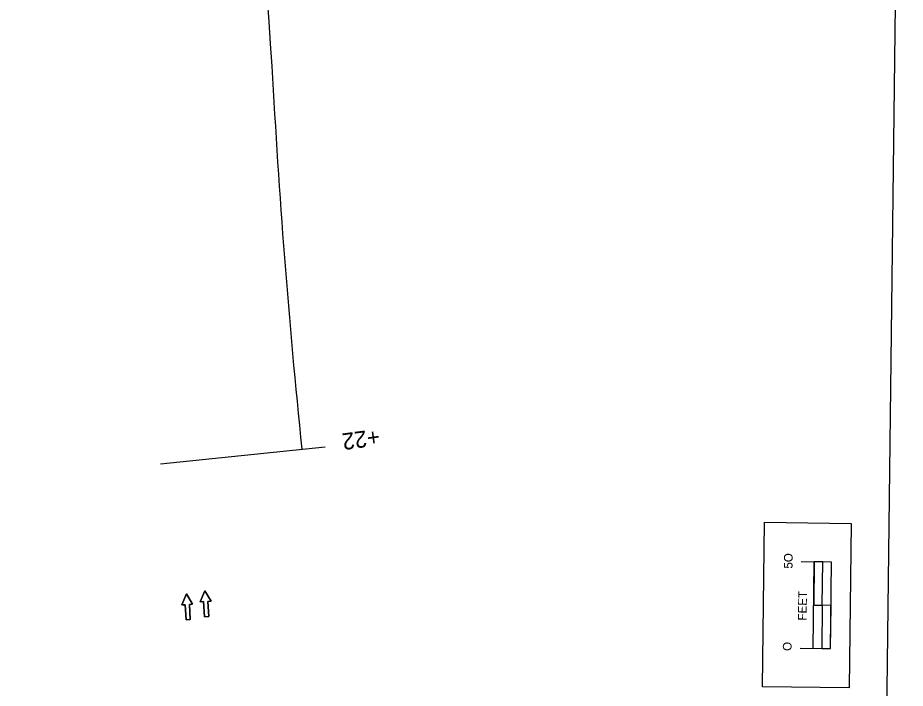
# Model space of a CAD drawing. Extents: x 4959127 to 4960275, y 3872379 to 3884458.
# Drawn here: x 4959633 to 4960146, y 3873092 to 3873480 of the extents above; entities that cross this region are included whole.
import ezdxf

# ---------------------------------------------------------------- set-up
doc = ezdxf.new("R2010")
doc.units = 0
for name, color, linetype in [('Alignment', 7, 'Continuous'), ('dsnCellElements', 7, 'Continuous'), ('dsnCellsScaleBlock', 7, 'Continuous'), ('Level 2', 7, 'Continuous'), ('Level 5', 7, 'Continuous'), ('NamedBoundary', 7, 'Continuous'), ('SheetText', 7, 'Continuous')]:
    doc.layers.add(name, color=color, linetype=linetype)

msp = doc.modelspace()

# ---------------------------------------------------------------- linework, layer by layer
at = {"layer": 'dsnCellElements'}
msp.add_lwpolyline([(4960063.53, 3873093.23), (4960064.7, 3873188.23), (4960114.69, 3873187.61), (4960113.53, 3873092.62)], close=True, dxfattribs=at)
msp.add_lwpolyline([(4960063.53, 3873093.23), (4960064.7, 3873188.23), (4960114.69, 3873187.61), (4960113.53, 3873092.62)], close=True, dxfattribs=at)
at = {"layer": 'dsnCellsScaleBlock'}
msp.add_line((4960103.11, 3873140.25), (4960093.11, 3873140.37), dxfattribs=at)
msp.add_line((4960103.11, 3873140.25), (4960093.11, 3873140.37), dxfattribs=at)
for points in [[(4960113.53, 3873092.62), (4960063.53, 3873093.23), (4960064.7, 3873188.23), (4960114.69, 3873187.61)], [(4960098.08, 3873140.31), (4960098.38, 3873165.31), (4960093.42, 3873165.37), (4960093.11, 3873140.37)], [(4960102.8, 3873115.25), (4960103.11, 3873140.25), (4960098.08, 3873140.31), (4960097.77, 3873115.32)]]:
    msp.add_lwpolyline(points, close=True, dxfattribs=at)
for points in [[(4960085.31, 3873115.47), (4960102.8, 3873115.25), (4960103.42, 3873165.25), (4960085.92, 3873165.46)], [(4960092.81, 3873115.38), (4960093.42, 3873165.37)]]:
    msp.add_lwpolyline(points, dxfattribs=at)
at = {"layer": 'Level 2'}
for points in [[(4959732.84, 3873132.06), (4959730.35, 3873131.9), (4959729.78, 3873140.63), (4959727.91, 3873140.51), (4959730.63, 3873146.95), (4959734.15, 3873140.91), (4959732.28, 3873140.79)], [(4959743.48, 3873133.82), (4959740.99, 3873133.66), (4959740.42, 3873142.39), (4959738.55, 3873142.27), (4959741.27, 3873148.71), (4959744.79, 3873142.67), (4959742.92, 3873142.55)]]:
    msp.add_lwpolyline(points, close=True, dxfattribs=at)
at = {"layer": 'Level 5'}
for points in [[(4959732.28, 3873140.79), (4959734.15, 3873140.91), (4959730.63, 3873146.95), (4959727.91, 3873140.51), (4959729.78, 3873140.63), (4959730.35, 3873131.9), (4959732.84, 3873132.06), (4959732.28, 3873140.79)], [(4959742.92, 3873142.55), (4959744.79, 3873142.67), (4959741.27, 3873148.71), (4959738.55, 3873142.27), (4959740.42, 3873142.39), (4959740.99, 3873133.66), (4959743.48, 3873133.82), (4959742.92, 3873142.55)]]:
    msp.add_lwpolyline(points, dxfattribs=at)
at = {"layer": 'NamedBoundary'}
msp.add_lwpolyline([(4959126.87, 3872391.44), (4960126.8, 3872379.18), (4960146.01, 3873946.56), (4959146.09, 3873958.82)], close=True, dxfattribs=at)
at = {"layer": 'SheetText'}
msp.add_line((4959715.57, 3873222.11), (4959810.73, 3873231.94), dxfattribs=at)
for centre, radius, start, end in [((4964204.08, 3873777.26), 4436.04, 178.83867, 184.20824), ((4964209.33, 3873686.58), 4435.55, 183.03493, 185.90104)]:
    msp.add_arc(centre, radius, start, end, dxfattribs=at)

# ---------------------------------------------------------------- texts
at = {"layer": 'Alignment'}
msp.add_text('+22', height=0.0167, rotation=185.901, dxfattribs=at).set_placement((4959777.19, 3873196.01))
at = {"layer": 'dsnCellsScaleBlock'}
for s, p in [('5O', (4960080.87, 3873161.45)), ('FEET', (4960089, 3873131.45)), ('O', (4960080.28, 3873113.9))]:
    msp.add_text(s, height=5, rotation=89.2975, dxfattribs=at).set_placement(p)
at = {"layer": 'SheetText'}
msp.add_text('+22', height=9.6, rotation=187.685, dxfattribs=at).set_placement((4959841.66, 3873242.38))

doc.saveas('drawing.dxf')
